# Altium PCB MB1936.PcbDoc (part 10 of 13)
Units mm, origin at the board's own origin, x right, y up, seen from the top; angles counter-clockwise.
Board outline 172 x 137 mm, 6 copper layers (Top Layer, Signal Layer 1, Signal Layer 2, Signal Layer 3, Signal Layer 4, Bottom Layer), stack 1.549 mm thick; 859 components, 672 nets, 3477 pads, 2222 vias.
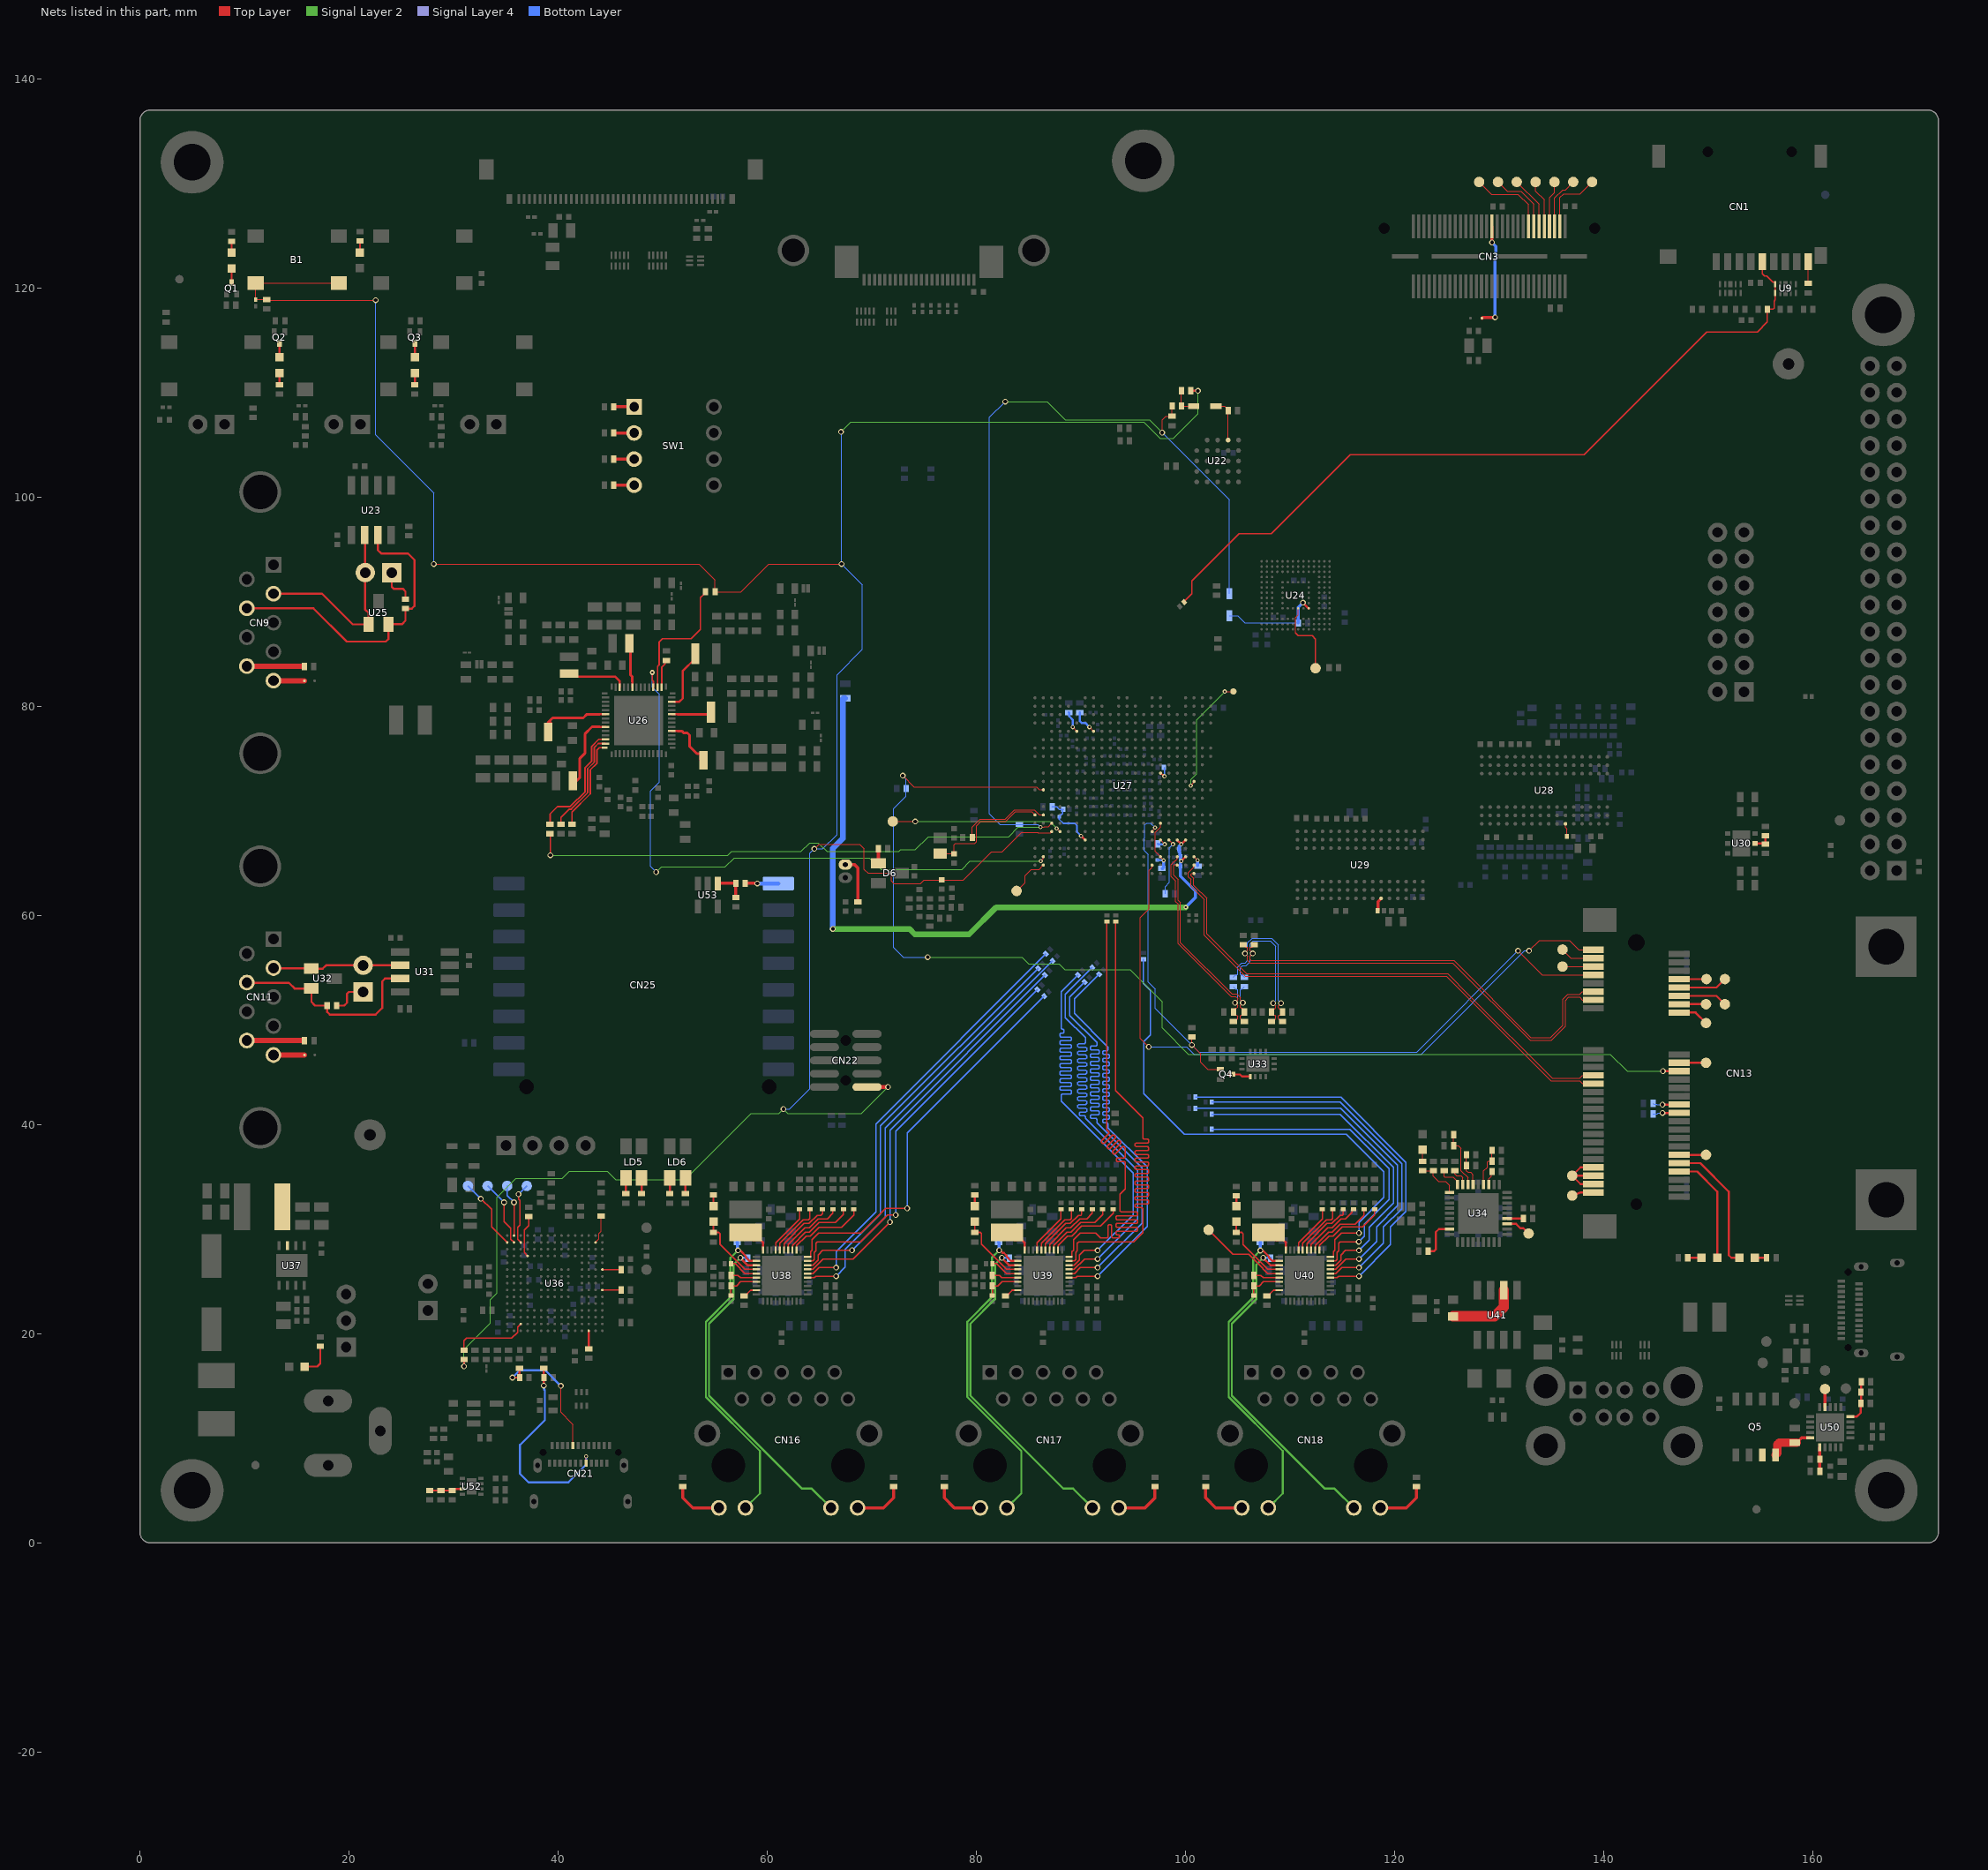
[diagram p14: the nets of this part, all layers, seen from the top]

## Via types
v1: diameter 0.55, hole 0.35, Top Layer to Bottom Layer, 1661 vias
v2: diameter 0.4, hole 0.2, Top Layer to Bottom Layer, tented both sides, 253 vias
v3: diameter 0.5, hole 0.2, Top Layer to Bottom Layer, 157 vias
v4: diameter 0.5, hole 0.25, Top Layer to Bottom Layer, 145 vias
v5: diameter 0.4, hole 0.2, Top Layer to Bottom Layer, 6 vias

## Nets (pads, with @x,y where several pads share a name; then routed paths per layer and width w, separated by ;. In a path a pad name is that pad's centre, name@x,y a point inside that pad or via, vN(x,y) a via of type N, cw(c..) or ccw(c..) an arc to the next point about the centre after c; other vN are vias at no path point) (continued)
NetC235_2: C235.2 C244.2 R267.1 U27.V7 | length 5.8
  Top Layer w0.2: v2(90,67.6) U27.V7@90.4,67.2
  Bottom Layer w0.15: R267.1@87.25,70.375 87.675,70.375 87.925,70.125 C235.2@88.238,70.125 ; C235.2@88.3,70.125 88.238,70.063 88.238,69.738 C244.2@87.925,69.425 87.925,69.175 88.3,68.8 89.4,68.8 89.6,68.6 89.6,67.999 v2(90,67.6)
NetC249_2: C249.2 C252.2 C260.2 R249.2 U27.V18 U27.V19 U27.Y19 | length 66.6
  Top Layer w0.2: U27.V18@99.2,67.2 v2(99.6,66.8) ; v2(99.6,65.2) U27.Y19@100,65.6 ; v2(99.6,66.8) U27.V19@100,67.2
  Signal Layer 2 w0.55: v1(66.275,58.7) 73.591,58.7 74.116,58.175 79.3,58.175 81.9,60.775 v2(100.025,60.775)
  Bottom Layer w0.3: v2(99.6,66.8) 99.397,66.597 99.397,66.347 C249.2@99.375,66.325 99.4,66.3 99.4,66.05 99.475,65.975 99.475,65.7 C252.2@99.5,65.675 99.5,65.326 99.6,65.227 v2(99.6,65.2) 99.6,65.173 99.5,65.073 C260.2@99.5,64.675 99.5,63.761 100.95,62.311 100.95,61.7 v2(100.025,60.775)
  Bottom Layer w0.55: v1(66.275,58.7) 66.275,66.4 67.225,67.35 67.225,80.705 67.27,80.75 R249.2@67.45,80.75
NetC251_2: C251.2 R286.2 U27.T16 U27.Y16 | length 5.5
  Top Layer w0.1: U27.T16@97.6,68.8 97.6,68.425 97.1,67.925 97.1,66.1 U27.Y16@97.6,65.6 97.6,65.575 97.906,65.269 v2(97.906,65.243)
  Bottom Layer w0.2: C251.2@97.3,65.3 97.329,65.272 97.878,65.272 v2(97.906,65.243)
  Bottom Layer w0.3: R286.2@97.795,64.475 97.9,64.58 v2@97.9,65.238
NetCN1_5: CN1.5 R13.1 R247.2 U9.1 U9.10 | length 74.7
  Top Layer w0.11: R247.2@99.862,89.962 99.862,89.987 100.621,90.746 100.621,91.996 105.11,96.485 108.185,96.485 115.75,104.05 138.1,104.05 149.825,115.775 154.675,115.775 155.64,116.74 R13.1@155.64,117.95 156.174,117.95 156.275,118.05 156.275,118.735 156.375,118.835 U9.1@156.375,119.52 156.375,120.496 156.33,120.541 156.174,120.541 155.59,121.125 155.35,121.125 155.15,121.325 CN1.5@155.15,122.5
NetCN1_9: CN1.9 R6.2 | length 2.1
  Top Layer w0.1: R6.2@159.55,120.425 CN1.9@159.55,122.5
NetCN3_32: CN3.32 SB1.1 | length 10.2
  Top Layer w0.3: SB1.1@128.35,117.1 128.425,117.175 v1(129.6,117.175) ; v1(129.3,124.34) CN3.32@129.3,125.87
  Bottom Layer w0.3: v1@129.3,124.339 129.675,123.964 129.675,122.783 129.6,122.708 v1(129.6,117.175)
NetCN3_46: CN3.46 TP1.1 | length 7.7
  Top Layer w0.1: TP1.1@128.075,130.125 129.25,128.95 131.8,128.95 132.8,127.95 CN3.46@132.8,125.87
NetCN3_48: CN3.48 TP2.1 | length 6.4
  Top Layer w0.1: TP2.1@129.875,130.125 130.76,129.24 132.06,129.24 133.3,128 CN3.48@133.3,125.87
NetCN3_50: CN3.50 TP3.1 | length 5.1
  Top Layer w0.1: TP3.1@131.675,130.125 133.8,128 CN3.50@133.8,125.87
NetCN3_52: CN3.52 TP4.1 | length 4.6
  Top Layer w0.1: TP4.1@133.475,130.125 133.475,129.245 134.3,128.42 CN3.52@134.3,125.87
NetCN3_54: CN3.54 TP5.1 | length 4.5
  Top Layer w0.1: CN3.54@134.8,125.87 134.8,128.65 135.275,129.125 TP5.1@135.275,130.125
NetCN3_56: CN3.56 TP6.1 | length 5.1
  Top Layer w0.1: CN3.56@135.3,125.87 135.3,128.6 136.075,129.375 136.325,129.375 TP6.1@137.075,130.125
NetCN3_58: CN3.58 TP7.1 | length 6.5
  Top Layer w0.1: CN3.58@135.8,125.87 135.8,128.625 136.15,128.975 137.725,128.975 TP7.1@138.875,130.125
NetCN9_2: CN9.2 JP1.2 U23.6 U25.1 | length 19
  Top Layer w0.2: CN9.2@12.77,90.75 17.425,90.75 20.354,87.821 U25.1@21.859,87.821 ; U23.6@21.549,96.316 21.549,89.226 21.869,88.906 21.869,87.831 U25.1@21.859,87.821 ; U25.1@21.844,87.806 U25.1@21.859,87.821 ; U25.1@21.869,87.821 U25.1@21.859,87.821
NetCN9_5: CN9.5 SB2.2 | length 3
  Top Layer w0.5: CN9.5@12.787,82.425 SB2.2@15.747,82.425
NetCN9_7: CN9.7 R40.1 U23.7 U25.2 | length 30
  Top Layer w0.2: CN9.7@10.23,89.365 16.585,89.365 19.775,86.175 23.525,86.175 23.769,86.419 U25.2@23.769,87.821 ; U23.7@22.764,96.361 22.764,94.921 23.081,94.603 25.621,94.603 26.254,93.971 26.254,89.581 26.004,89.331 25.399,89.331 25.399,88.181 25.049,87.831 U25.2@23.769,87.831
NetCN9_9: CN9.9 R50.2 | length 5.5
  Top Layer w0.2: R50.2@15.737,83.81 R50.2@15.747,83.8
  Top Layer w0.5: CN9.9@10.247,83.81 R50.2@15.737,83.81
NetCN11_2: CN11.2 JP2.2 U31.6 U32.1 | length 12.3
  Top Layer w0.2: CN11.2@12.77,54.925 16.38,54.925 U32.1@16.405,54.9 17.48,54.9 17.8,55.22 JP2.2@21.355,55.22 U31.6@24.89,55.22
NetCN11_5: CN11.5 SB3.2 | length 3
  Top Layer w0.5: CN11.5@12.79,46.65 SB3.2@15.75,46.65
NetCN11_7: CN11.7 R80.1 U31.7 U32.2 | length 19.9
  Top Layer w0.2: CN11.7@10.23,53.54 14.26,53.54 14.8,53 U32.2@16.405,53 16.405,51.72 16.755,51.37 R80.1@17.905,51.37 17.905,50.765 18.155,50.515 22.545,50.515 23.178,51.148 23.178,53.688 23.44,53.95 U31.7@24.89,53.95
NetCN11_9: CN11.9 R86.2 | length 5.5
  Top Layer w0.2: R86.2@15.74,48.035 R86.2@15.75,48.025
  Top Layer w0.5: CN11.9@10.25,48.035 R86.2@15.74,48.035
NetCN12_1: CN12.1 R66.1 | length 4.6
  Top Layer w0.3: CN12.1@67.475,64.85 68.35,64.85 68.675,64.525 R66.1@68.675,61.295
NetCN13_3: CN13.3 TP14.1 | length 3.3
  Top Layer w0.1: TP14.1@136.05,56.725 136.05,56.7 136.85,55.9 CN13.3@139,55.9
NetCN13_5: CN13.5 TP15.1 | length 2.4
  Top Layer w0.1: 136.55,55.1 CN13.5@139,55.1
NetCN13_8: CN13.8 TP16.1 | length 2.6
  Top Layer w0.2: CN13.8@147.243,53.9 TP16.1@149.818,53.9
NetCN13_10: CN13.10 TP17.1 | length 4.7
  Top Layer w0.2: CN13.10@147.2,53.1 150.775,53.1 TP17.1@151.575,53.9
NetCN13_12: CN13.12 TP19.1 | length 4.7
  Top Layer w0.2: CN13.12@147.2,52.3 150.775,52.3 TP19.1@151.575,51.5
NetCN13_14: CN13.14 TP18.1 | length 2.6
  Top Layer w0.2: CN13.14@147.2,51.5 TP18.1@149.775,51.5
NetCN13_16: CN13.16 TP20.1 | length 3
  Top Layer w0.2: CN13.16@147.2,50.7 148.775,50.7 TP20.1@149.775,49.7
NetCN13_20: CN13.20 TP21.1 | length 2.6
  Top Layer w0.2: CN13.20@147.2,45.9 TP21.1@149.775,45.9
NetCN13_30: CN13.30 R290.1 | length 2.6
  Top Layer w0.2: v1(145.614,41.9) CN13.30@147.2,41.9
  Bottom Layer w0.1: R290.1@144.7,42.025 144.791,41.934 145.046,41.934 145.08,41.9 v1(145.614,41.9)
NetCN13_32: CN13.32 R291.1 | length 2.5
  Top Layer w0.2: v1(145.614,41.1) CN13.32@147.2,41.1
  Bottom Layer w0.1: R291.1@144.7,41 145.107,41 145.207,41.1 v1(145.614,41.1)
NetCN13_42: CN13.42 TP23.1 | length 2.6
  Top Layer w0.2: CN13.42@147.2,37.1 TP23.1@149.775,37.1
NetCN13_44: CN13.44 LD10.2 | length 13
  Top Layer w0.2: CN13.44@147.2,36.3 149.225,36.3 151.937,33.587 151.937,27.513 152.2,27.25 LD10.2@152.875,27.25
NetCN13_45: CN13.45 CN13.47 CN13.49 TP24.1 | length 6.7
  Top Layer w0.2: CN13.49@139,34.3 137.775,34.3 TP24.1@136.975,35.1 ; CN13.47@139,35.1 TP24.1@136.975,35.1 ; CN13.45@139,35.9 137.775,35.9 TP24.1@136.975,35.1
NetCN13_46: CN13.46 LED2.2 | length 10.8
  Top Layer w0.2: CN13.46@147.2,35.5 148.921,35.5 150.85,33.571 LED2.2@150.85,27.25
NetCN13_51: CN13.51 TP25.1 | length 2.1
  Top Layer w0.2: TP25.1@136.975,33.2 137.775,33.5 CN13.51@139,33.5
NetCN16_11: CN16.11 R233.1 | length 4.9
  Top Layer w0.3: R233.1@51.925,5.375 51.925,4.3 52.885,3.34 CN16.11@55.37,3.34
NetCN16_12: CN16.12 R319.2 U38.32 | length 31.6
  Top Layer w0.2: v1(57.196,27.965) 57.263,27.898 57.449,27.898 57.961,27.386 57.961,27.289 58.3,26.95 U38.32@58.95,26.95
  Signal Layer 2 w0.2: v1(57.196,27.965) 56.475,27.244 56.475,23.475 54.125,21.125 54.125,13.951 59.3,8.776 59.3,4.73 CN16.12@57.91,3.34
  Bottom Layer w0.3: R319.2@57.125,28.725 57.161,28.689 57.161,28 v1(57.196,27.965)
NetCN16_13: CN16.13 R322.2 U38.33 | length 33.1
  Top Layer w0.2: v1(57.425,27.25) 57.425,27.233 58.108,26.55 U38.33@58.95,26.55
  Signal Layer 2 w0.2: v1(57.425,27.25) 56.775,26.6 56.775,23.297 54.425,20.947 54.425,14.075 63.325,5.175 64.255,5.175 CN16.13@66.09,3.34
  Bottom Layer w0.2: v1(57.425,27.25) 58.1,27.25 R322.2@58.15,27.2
NetCN16_14: CN16.14 R234.2 | length 4.9
  Top Layer w0.3: CN16.14@68.63,3.34 71.115,3.34 72.075,4.3 R234.2@72.075,5.375
NetCN17_11: CN17.11 R235.1 | length 4.9
  Top Layer w0.3: R235.1@76.925,5.375 76.925,4.3 77.885,3.34 CN17.11@80.37,3.34
NetCN17_12: CN17.12 R317.2 U39.32 | length 31.6
  Top Layer w0.2: v1(82.177,27.969) 82.272,27.969 82.516,27.725 82.622,27.725 82.9,27.447 82.9,27.35 83.3,26.95 U39.32@83.95,26.95
  Signal Layer 2 w0.2: v1(82.177,27.969) 81.475,27.267 81.475,23.475 79.125,21.125 79.125,13.951 84.3,8.776 84.3,4.73 CN17.12@82.91,3.34
  Bottom Layer w0.3: R317.2@82.125,28.725 82.151,28.699 82.151,27.995 v1(82.177,27.969)
NetCN17_13: CN17.13 R321.2 U39.33 | length 33.1
  Top Layer w0.2: v1(82.425,27.25) 82.425,27.233 83.108,26.55 U39.33@83.95,26.55
  Signal Layer 2 w0.2: v1(82.425,27.25) 81.775,26.6 81.775,23.297 79.425,20.947 79.425,14.075 88.325,5.175 89.255,5.175 CN17.13@91.09,3.34
  Bottom Layer w0.2: v1(82.425,27.25) 83.1,27.25 R321.2@83.15,27.2
NetCN17_14: CN17.14 R236.2 | length 4.9
  Top Layer w0.3: CN17.14@93.63,3.34 96.115,3.34 97.075,4.3 R236.2@97.075,5.375
NetCN18_11: CN18.11 R237.1 | length 4.9
  Top Layer w0.3: R237.1@101.925,5.375 101.925,4.3 102.885,3.34 CN18.11@105.37,3.34
NetCN18_12: CN18.12 R315.2 U40.32 | length 31.6
  Top Layer w0.2: v1(107.148,27.951) 107.215,27.884 107.463,27.884 107.961,27.386 107.961,27.289 108.3,26.95 U40.32@108.95,26.95
  Signal Layer 2 w0.2: v1(107.148,27.951) 106.475,27.277 106.475,23.475 104.125,21.125 104.125,13.951 109.3,8.776 109.3,4.73 CN18.12@107.91,3.34
  Bottom Layer w0.3: R315.2@107.125,28.725 107.137,28.713 107.137,27.963 v1(107.148,27.951)
NetCN18_13: CN18.13 R320.2 U40.33 | length 33.1
  Top Layer w0.2: v1(107.425,27.25) 107.425,27.233 108.108,26.55 U40.33@108.95,26.55
  Signal Layer 2 w0.2: v1(107.425,27.25) 106.775,26.6 106.775,23.297 104.425,20.947 104.425,14.075 113.325,5.175 114.255,5.175 CN18.13@116.09,3.34
  Bottom Layer w0.2: v1(107.425,27.25) 108.1,27.25 R320.2@108.15,27.2
NetCN18_14: CN18.14 R238.2 | length 4.9
  Top Layer w0.3: CN18.14@118.63,3.34 121.115,3.34 122.075,4.3 R238.2@122.075,5.375
NetCN21_A5: CN21.A5 R217.2 R221.1 | length 13.6
  Top Layer w0.1: v1(40.252,15.008) 40.25,15.006 40.25,12.475 41.25,11.475 ; 41,11.725 41.25,11.475 ; CN21.A5@41.415,9.31 41.415,11.31 41.25,11.475
  Top Layer w0.2: v1(35.63,15.8) R221.1@36.305,15.8 R217.2@36.305,16.7
  Bottom Layer w0.2: v1(35.63,15.8) 36.33,16.5 38.76,16.5 v1(40.252,15.008)
NetCN21_B5: CN21.B5 R218.2 R222.1 | length 19.9
  Top Layer w0.1: CN21.B5@42.665,7.61 v5(42.665,8.27)
  Top Layer w0.2: v1(38.625,15.03) R222.1@38.625,15.8 R218.2@38.625,16.7
  Bottom Layer w0.2: v1(38.625,15.03) 38.652,15.003 38.652,14.644 38.725,14.572 38.725,11.725 36.35,9.35 36.35,6.6 37.175,5.775 40.975,5.775 42.665,7.465 v5(42.665,8.27)
NetCN25_1: CN25.1 R243.1 | length 3.2
  Top Layer w0.3: R243.1@57.887,63.063 59.022,63.063 v1(59.04,63.045)
  Bottom Layer w0.4: v1@59.045,63.04 CN25.1@61.055,63.04
NetD1_1: D1.1 R23.1 U22.A4 | length 4.2
  Top Layer w0.1: D1.1@102.9,108.7 103.736,108.7 104.066,108.37 U22.A4@104.066,105.441
NetD1_2: D1.2 R21.2 R22.2 | length 2.6
  Top Layer w0.1: R21.2@99.609,110.15 R22.2@99.609,108.7 D1.2@100.76,108.7
NetD5_1: D5.1 R248.1 U24.K5 | length 9.8
  Top Layer w0.2: v1(111.225,89.9) U24.K5@111.775,89.35
  Bottom Layer w0.1: D5.1@104.175,88.63 104.995,88.63 105.675,87.95 R248.1@110.775,87.95
  Bottom Layer w0.3: R248.1@110.775,87.95 110.775,89.45 v1(111.225,89.9)
NetD6_1: D6.1 R67.1 | length 1.4
  Top Layer w0.3: D6.1@70.625,64.975 R67.1@70.625,66.375
NetJP1_1: JP1.1 R40.2 | length 3.6
  Top Layer w0.2: JP1.1@24.089,92.781 24.089,91.411 24.269,91.231 25.133,91.231 25.399,90.965 R40.2@25.399,90.231
NetJP2_1: JP2.1 R80.2 | length 3.6
  Top Layer w0.2: R80.2@18.805,51.37 19.539,51.37 19.805,51.636 19.805,52.5 19.985,52.68 JP2.1@21.355,52.68
NetL1_1: L1.1 U26.37 | length 4.2
  Top Layer w0.21: U26.37@47.1,81.797 47.1,82.352
  Top Layer w0.25: L1.1@46.9,85.962 46.9,83 47.1,82.8 47.1,82.352
NetL2_1: L2.1 U26.26 | length 5.7
  Top Layer w0.2: U26.26@51.117,80.427 51.6,80.427 51.925,80.752 51.925,83.387 53.05,84.512 L2.1@53.05,85.027
NetL3_1: L3.1 U26.40 | length 5.9
  Top Layer w0.15: L3.1@40.898,82.989 L3.1@41.05,82.837
  Top Layer w0.21: L3.1@41.05,83.102 41.335,82.817 43.11,82.817 45.465,82.817 45.9,82.382 U26.40@45.9,81.797
NetL4_1: L4.1 U26.23 | length 3.8
  Top Layer w0.15: L4.1@54.56,78.712 L4.1@54.56,79.227
  Top Layer w0.21: U26.23@50.87,79.227 51.425,79.227
  Top Layer w0.25: 51.425,79.227 54.2,79.227
NetL5_1: L5.1 U26.48 | length 7.2
  Top Layer w0.15: L5.1@38.818,77.275 L5.1@39.07,77.527 ; L5.1@39.29,77.412 L5.1@39.29,77.927
  Top Layer w0.21: 43.975,79.227 U26.48@44.53,79.227
  Top Layer w0.25: 39.025,78.427 39.475,78.877 42.4,78.877 42.75,79.227 43.975,79.227 ; L5.1@39.29,77.927 39.29,78.442
NetL6_1: L6.1 U26.19 | length 5.7
  Top Layer w0.15: L6.1@53.63,74.37 L6.1@53.63,74.852 ; L6.1@53.85,74.852 L6.1@54.102,74.599
  Top Layer w0.21: U26.19@50.87,77.627 51.425,77.627
  Top Layer w0.25: 51.425,77.627 51.823,77.627 51.998,77.452 52.35,77.452 52.575,77.227 52.575,76.152 53.271,75.456 53.625,75.456 53.63,75.451 L6.1@53.63,74.852
NetL7_1: L7.1 U26.51 | length 7.4
  Top Layer w0.21: 43.975,78.027 U26.51@44.53,78.027
  Top Layer w0.25: L7.1@41.625,73.252 L7.1@41.625,73.496 ; L7.1@41.675,72.777 42.075,73.177 42.075,75.011 42.55,75.486 42.55,77.33 43.247,78.027 43.975,78.027
NetL8_1: L8.1 U37.7
NetL12_2: L12.2 U41.2 | length 6.8
  Top Layer w1: L12.2@125.575,21.65 129.55,21.65 130.43,22.53 U41.2@130.43,24.15
NetLD1_1: LD1.1 R3.2 | length 0.9
  Top Layer w0.2: LD1.1@21.047,123.55 R3.2@21.047,124.475
NetLD2_1: LD2.1 R20.1 | length 1
  Top Layer w0.2: R20.1@26.287,110.75 LD2.1@26.287,111.7
NetLD2_2: LD2.2 Q3.3 | length 1.2
  Top Layer w0.2: LD2.2@26.287,113.5 Q3.3@26.287,114.7
NetLD3_1: LD3.1 R19.1 | length 1
  Top Layer w0.2: R19.1@13.363,110.75 LD3.1@13.363,111.7
NetLD3_2: LD3.2 Q2.3 | length 1.3
  Top Layer w0.2: LD3.2@13.363,113.35 Q2.3@13.363,114.7
NetLD4_1: LD4.1 R4.2 | length 1.1
  Top Layer w0.2: LD4.1@8.773,123.35 R4.2@8.773,124.45
NetLD4_2: LD4.2 Q1.3 | length 1.2
  Top Layer w0.2: Q1.3@8.773,120.5 LD4.2@8.773,121.7
NetLD5_1: LD5.1 R131.1 | length 1.5
  Top Layer w0.2: R131.1@47.975,33.375 LD5.1@47.975,34.9
NetLD5_2: LD5.2 R130.2 | length 1.5
  Top Layer w0.2: R130.2@46.475,33.375 LD5.2@46.475,34.9
NetLD6_1: LD6.1 R133.1 | length 1.5
  Top Layer w0.2: R133.1@52.175,33.375 LD6.1@52.175,34.9
NetLD6_2: LD6.2 R132.1 | length 1.5
  Top Layer w0.2: R132.1@50.675,33.375 LD6.2@50.675,34.9
NetLD7_1: LD7.1 R158.2 U38.34 | length 7.2
  Top Layer w0.15: LD7.1@54.85,30.695 R158.2@54.85,29.67 55.382,29.67 55.47,29.582 55.47,28.555 57.875,26.15 U38.34@58.95,26.15
NetLD7_2: LD7.2 R126.1 | length 1.1
  Top Layer w0.2: LD7.2@54.85,32.195 R126.1@54.85,33.27
NetLD8_1: LD8.1 R159.2 U39.34 | length 7.2
  Top Layer w0.15: LD8.1@79.85,30.695 R159.2@79.85,29.67 80.382,29.67 80.47,29.582 80.47,28.555 82.875,26.15 U39.34@83.95,26.15
NetLD8_2: LD8.2 R127.1 | length 0.9
  Top Layer w0.2: LD8.2@79.85,32.325 R127.1@79.85,33.27
NetLD9_1: LD9.1 R160.2 U40.34 | length 7.2
  Top Layer w0.15: LD9.1@104.85,30.695 R160.2@104.85,29.67 105.38,29.67 105.5,29.55 105.5,28.525 107.875,26.15 U40.34@108.95,26.15
NetLD9_2: LD9.2 R128.1 | length 0.8
  Top Layer w0.2: LD9.2@104.85,32.375 R128.1@104.85,33.17
NetLD10_1: LD10.1 R172.2 | length 1.1
  Top Layer w0.2: LD10.1@154.525,27.25 R172.2@155.575,27.25
NetLD11_1: LD11.1 R210.1 | length 3.2
  Top Layer w0.2: LD11.1@15.775,16.85 16.95,16.85 17.25,17.15 R210.1@17.25,18.8
NetLD12_1: LD12.1 R101.1 | length 1.1
  Top Layer w0.1: R101.1@122.675,36.475 LD12.1@122.675,37.575
NetLE1_1: LE1.1 U38.30 | length 2.8
  Top Layer w0.2: LE1.1@57.925,29.675 58.675,28.925 59.375,28.925 59.6,28.7 U38.30@59.6,28
NetLE2_1: LE2.1 U39.30 | length 2.8
  Top Layer w0.2: LE2.1@82.925,29.675 83.675,28.925 84.375,28.925 84.6,28.7 U39.30@84.6,28
NetLE3_1: LE3.1 U40.30 | length 2.8
  Top Layer w0.2: LE3.1@107.925,29.675 108.675,28.925 109.375,28.925 109.6,28.7 U40.30@109.6,28
NetLED2_1: LED2.1 R171.1 | length 1.3
  Top Layer w0.2: R171.1@148.025,27.25 LED2.1@149.3,27.25
NetQ4_3: Q4.3 U33.1 | length 1.8
  Top Layer w0.2: Q4.3@104.425,44.79 105.2,44.79 105.4,44.59 U33.1@106.175,44.59
NetQ5_7: Q5.7 Q5.8 R225.2 U50.10 | length 4.5
  Top Layer w0.3: R225.2@158.43,9.575 158.905,10.05 U50.10@159.725,10.05
  Top Layer w0.8: Q5.8@156.425,8.4 156.6,8.575 156.6,9.399 156.776,9.575 R225.2@158.43,9.575
NetR38_2: R38.2 U26.31 | length 12.7
  Top Layer w0.15: U26.31@49.5,81.797 49.5,83.8 49.65,83.95 49.65,86.125 49.975,86.45 52.725,86.45 53.6,87.325 53.6,90.357 53.918,90.675 53.92,90.675 54.1,90.855 R38.2@54.1,90.95
NetR46_2: R46.2 U26.30 | length 2.8
  Top Layer w0.15: U26.30@49.9,81.797 49.9,83.697 50.232,84.029 50.232,84.257 R46.2@50.35,84.375
NetR59_2: R59.2 U26.54 | length 11.4
  Top Layer w0.15: R59.2@39.225,68.7 39.225,69.675 39.95,70.4 41.15,70.4 42.575,71.825 42.575,74.125 43.212,74.762 43.212,76.162 43.877,76.827 U26.54@44.53,76.827
NetR60_2: R60.2 U26.55 | length 10
  Top Layer w0.15: R60.2@40.275,68.7 40.275,69.353 41.072,70.15 41.254,70.15 42.825,71.721 42.825,74.021 43.462,74.659 43.462,76.059 43.831,76.427 U26.55@44.53,76.427
NetR61_2: R61.2 U26.56 | length 8.9
  Top Layer w0.15: R61.2@41.325,68.7 41.325,69.868 43.075,71.618 43.075,73.918 43.712,74.555 43.712,75.812 43.927,76.027 U26.56@44.455,76.027
NetR62_2: R62.2 R65.1 U30.5 | length 1.7
  Top Layer w0.2: U30.5@154.455,66.875 155.405,66.875 155.455,66.925 R62.2@155.455,67.6
NetR63_2: R63.2 U28.F9 | length 1.3
  Top Layer w0.09: U28.F9@136.325,68.75 136.325,68.4 136.475,68.25 R63.2@136.475,67.55
NetR68_1: R68.1 SW1.1 | length 1.9
  Top Layer w0.3: R68.1@45.325,108.625 SW1.1@47.265,108.625
NetR71_1: R71.1 SW1.2 | length 1.9
  Top Layer w0.3: R71.1@45.325,106.125 SW1.2@47.265,106.125
NetR73_2: R73.2 U29.F9 | length 1.3
  Top Layer w0.3: R73.2@118.375,60.425 118.375,60.475 118.418,60.517 118.418,61.317 118.7,61.599 U29.F9@118.7,61.625
NetR76_1: R76.1 SW1.3 | length 1.9
  Top Layer w0.3: R76.1@45.325,103.625 SW1.3@47.265,103.625
NetR79_1: R79.1 SW1.4 | length 1.9
  Top Layer w0.3: R79.1@45.325,101.125 SW1.4@47.265,101.125
NetR95_2: R95.2 R97.1 U34.25 | length 5.6
  Top Layer w0.1: R95.2@125.625,39.025 R97.1@125.625,37.975 126.1,37.975 126.35,37.725 126.35,35.575 127,34.925 U34.25@127,34.25
NetR98_2: R98.2 R100.1 U34.22 | length 3.8
  Top Layer w0.1: U34.22@128.5,34.25 128.5,35.554 128.85,35.904 128.85,36.4 128.95,36.5 R100.1@129.3,36.5 R98.2@129.3,37.525
NetR99_1: R99.1 R105.2 U34.24 | length 3.3
  Top Layer w0.1: R99.1@126.85,37.105 R105.2@126.85,36.08 126.85,35.584 127,35.434 127.256,35.434 127.495,35.195 127.495,34.255 U34.24@127.5,34.25
NetR101_2: R101.2 R102.2 U34.28 | length 4.1
  Top Layer w0.1: R101.2@122.675,35.575 R102.2@123.7,35.575 123.7,35.05 124.2,34.55 124.884,34.55 125.25,34.184 U34.28@125.25,33.5
NetR103_1: R103.1 U34.27 | length 2.3
  Top Layer w0.1: R103.1@124.725,35.575 124.725,35.034 124.784,34.975 125.575,34.975 126,34.55 U34.27@126,34.25
NetR104_2: R104.2 U34.26 | length 1.9
  Top Layer w0.1: R104.2@125.75,35.575 125.75,35.25 125.9,35.1 126.341,35.1 126.5,34.941 U34.26@126.5,34.25
NetR106_1: R106.1 U34.21 | length 1.4
  Top Layer w0.1: U34.21@129,34.25 129,34.825 129.234,35.059 129.234,35.434 R106.1@129.3,35.5
NetR135_2: R135.2 U38.27 | length 4.8
  Top Layer w0.11: U38.27@60.8,28 60.8,28.675 63.075,30.95 R135.2@63.075,31.9
NetR136_2: R136.2 U38.26 | length 5.4
  Top Layer w0.11: U38.26@61.2,28 61.2,28.65 63.45,30.9 63.95,30.9 64.075,31.025 R136.2@64.075,31.9
NetR137_2: R137.2 U38.25 | length 5.9
  Top Layer w0.11: U38.25@61.6,28 61.6,28.6 63.525,30.525 63.975,30.525 64.775,31.325 65.125,31.325 65.275,31.475 ; 65.275,31.5 65.275,31.475 ; R137.2@65.275,31.9 65.275,31.475
NetR138_2: R138.2 U38.24 | length 6.4
  Top Layer w0.11: U38.24@62,28 62,28.525 63.587,30.113 64.012,30.113 64.875,30.975 65.75,30.975 66.275,31.5 R138.2@66.275,31.9
NetR139_2: R139.2 U38.23 | length 7
  Top Layer w0.11: U38.23@62.4,28 62.4,28.45 63.662,29.713 64.037,29.713 64.95,30.625 66.5,30.625 67.275,31.4 R139.2@67.275,31.9
NetR140_2: R140.2 U38.22 | length 7.7
  Top Layer w0.11: U38.22@62.8,28 62.8,28.425 63.712,29.338 64.112,29.338 64.95,30.175 67.1,30.175 68.275,31.35 R140.2@68.275,31.9
NetR141_2: R141.2 U39.27 | length 4.8
  Top Layer w0.11: U39.27@85.8,28 85.8,28.675 88.075,30.95 R141.2@88.075,31.9
NetR142_2: R142.2 U39.26 | length 5.4
  Top Layer w0.11: U39.26@86.2,28 86.2,28.65 88.45,30.9 88.95,30.9 89.075,31.025 R142.2@89.075,31.9
NetR143_2: R143.2 U39.25 | length 5.7
  Top Layer w0.11: U39.25@86.6,28 86.6,28.6 88.525,30.525 88.975,30.525 89.775,31.325 90.011,31.325 90.075,31.389 R143.2@90.075,31.9
NetR144_2: R144.2 U39.24 | length 6.2
  Top Layer w0.11: U39.24@87,28 87,28.525 88.587,30.113 89.012,30.113 89.875,30.975 90.55,30.975 91.075,31.5 R144.2@91.075,31.9
NetR145_2: R145.2 U39.23 | length 6.8
  Top Layer w0.11: U39.23@87.4,28 87.4,28.45 88.662,29.713 89.037,29.713 89.95,30.625 91.3,30.625 92.075,31.4 R145.2@92.075,31.9
NetR146_2: R146.2 U39.22 | length 7.4
  Top Layer w0.11: U39.22@87.8,28 87.8,28.425 88.712,29.338 89.112,29.338 90.075,30.3 91.875,30.3 93.075,31.5 R146.2@93.075,31.9
NetR147_2: R147.2 U40.27 | length 4.8
  Top Layer w0.11: U40.27@110.8,28 110.8,28.675 113.075,30.95 R147.2@113.075,31.9
NetR148_2: R148.2 U40.26 | length 5.4
  Top Layer w0.11: U40.26@111.2,28 111.2,28.65 113.45,30.9 113.95,30.9 114.075,31.025 R148.2@114.075,31.9
NetR149_2: R149.2 U40.25 | length 5.7
  Top Layer w0.11: U40.25@111.6,28 111.6,28.6 113.525,30.525 113.975,30.525 114.775,31.325 115.011,31.325 115.075,31.389 R149.2@115.075,31.9
NetR150_2: R150.2 U40.24 | length 6.1
  Top Layer w0.11: U40.24@112,28 112,28.525 113.587,30.113 114.012,30.113 114.875,30.975 115.3,30.975 115.924,31.599 115.924,31.755 116.069,31.9 R150.2@116.075,31.9
NetR151_2: R151.2 U40.23 | length 6.9
  Top Layer w0.11: U40.23@112.4,28 112.4,28.45 113.662,29.713 114.037,29.713 114.8,30.475 116.233,30.475 117.075,31.317 R151.2@117.075,31.9
NetR152_2: R152.2 U40.22 | length 7.5
  Top Layer w0.11: U40.22@112.8,28 112.8,28.425 113.712,29.338 114.112,29.338 114.975,30.2 116.925,30.2 118.075,31.35 R152.2@118.075,31.9
NetR155_2: R155.2 U36.B14 | length 2.7
  Top Layer w0.1: U36.B14@43.575,28.725 43.9,29.05 43.9,29.575 44.1,29.775 R155.2@44.1,31.25
NetR156_1: R156.1 U36.D4 | length 4.1
  Top Layer w0.12: U36.D4@37.075,27.425 36.75,27.75 36.75,29.9 37.2,30.35 R156.1@37.2,31.2
NetR157_1: R157.1 U34.13 | length 1.6
  Top Layer w0.2: U34.13@130.75,31 R157.1@132.311,31
NetR161_2: R161.2 U38.20 | length 38
  Top Layer w0.11: U38.20@63.85,27.35 64.1,27.35 64.145,27.395 64.145,27.837 64.28,27.972 64.28,28.98 64.915,29.615 68.965,29.615 71.325,31.975 v1(73.375,31.975)
  Bottom Layer w0.11: v1(73.375,31.975) 73.375,39.175 R161.2@86.475,52.275
NetR162_2: R162.2 U39.20 | length 60.5
  Top Layer w0.11: U39.20@88.85,27.35 89.1,27.35 89.145,27.395 89.145,27.837 89.28,27.972 89.28,28.98 89.915,29.615 91.385,29.615 91.85,29.15 92.431,29.15 92.486,29.15 92.577,29.241 92.577,30.329 92.668,30.42 92.85,30.42 92.941,30.329 92.941,29.241 93.032,29.15 93.277,29.15 93.6,29.15 93.673,29.223 93.673,29.352 93.582,29.443 93.44,29.443 93.349,29.534 93.349,29.716 93.44,29.807 95.34,29.807 95.431,29.898 95.431,30.08 95.34,30.171 93.44,30.171 93.349,30.262 93.349,30.444 93.44,30.535 95.34,30.535 95.431,30.626 95.431,30.808 95.34,30.899 93.44,30.899 93.349,30.99 93.349,31.172 93.44,31.263 95.34,31.263 95.431,31.354 95.431,31.536 95.34,31.627 93.836,31.627 93.745,31.718 93.745,32.005 93.745,33.32 94.25,33.825 94.25,36.356 94.159,36.447 93.483,36.447 93.392,36.538 93.392,36.72 93.483,36.811 94.159,36.811 94.25,36.902 94.25,37.425 94.25,37.725 94.103,37.872 93.975,37.872 93.256,37.153 93.128,37.153 92.999,37.282 92.999,37.411 93.8,38.211 93.8,38.34 93.671,38.469 93.542,38.469 92.741,37.668 92.613,37.668 92.484,37.797 92.484,37.925 93.285,38.726 93.285,38.855 93.156,38.983 93.027,38.983 92.227,38.183 92.098,38.183 91.969,38.311 91.969,38.44 92.688,39.159 92.688,39.287 92.596,39.379 92.557,39.418 92.475,39.5 R162.2@92.475,59.4
NetR163_2: R163.2 U40.20 | length 50.8
  Top Layer w0.11: U40.20@113.85,27.35 114.1,27.35 114.145,27.395 114.145,27.837 114.28,27.972 114.28,28.98 114.915,29.615 v1(116.58,29.615)
  Bottom Layer w0.11: R163.2@95.975,55.8 95.975,53.514 96.65,52.839 96.65,48.575 96.013,47.938 96.013,42.93 99.868,39.075 115.375,39.075 118.968,35.482 118.968,33.018 116.58,30.63 v1(116.58,29.615)
NetR164_2: R164.2 U38.19 | length 38.3
  Top Layer w0.11: U38.19@63.85,26.95 64.37,26.95 64.49,27.07 64.49,27.78 64.64,27.93 64.64,28.64 64.79,28.79 68.915,28.79 71.475,31.35 v1(72.275,31.35)
  Bottom Layer w0.11: v1(72.275,31.35) 72.275,39.35 R164.2@85.838,52.913
NetR165_2: R165.2 U39.19 | length 60.9
  Top Layer w0.11: U39.19@88.85,26.95 89.37,26.95 89.49,27.07 89.49,27.78 89.64,27.93 89.64,28.64 89.79,28.79 95.015,28.79 95.9,29.675 95.9,31.9 95.9,31.955 95.809,32.046 95.27,32.046 95.179,32.137 95.179,32.319 95.27,32.41 96.37,32.41 96.461,32.501 96.461,32.683 96.37,32.774 95.27,32.774 95.179,32.865 95.179,33.047 95.27,33.138 96.37,33.138 96.461,33.229 96.461,33.411 96.37,33.502 95.27,33.502 95.179,33.593 95.179,33.775 95.27,33.866 96.37,33.866 96.461,33.957 96.461,34.139 96.37,34.23 95.27,34.23 95.179,34.321 95.179,34.503 95.27,34.594 96.37,34.594 96.461,34.685 96.461,34.867 96.37,34.958 95.27,34.958 95.179,35.049 95.179,35.231 95.27,35.322 96.37,35.322 96.461,35.413 96.461,35.595 96.37,35.686 95.27,35.686 95.179,35.777 95.179,35.959 95.27,36.05 96.37,36.05 96.461,36.141 96.461,36.323 96.37,36.414 95.27,36.414 95.179,36.505 95.179,36.687 95.27,36.778 96.37,36.778 96.461,36.869 96.461,37.051 96.37,37.142 95.27,37.142 95.179,37.233 95.179,37.415 95.27,37.506 96.37,37.506 96.461,37.597 96.461,37.779 96.37,37.87 95.27,37.87 95.179,37.961 95.179,38.143 95.27,38.234 96.37,38.234 96.461,38.325 96.461,38.507 96.37,38.598 95.991,38.598 95.9,38.689 95.9,38.762 95.9,40.65 93.319,43.231 93.319,59.394 R165.2@93.325,59.4
NetR166_2: R166.2 U40.19 | length 31
  Top Layer w0.11: U40.19@113.85,26.95 114.37,26.95 114.49,27.07 114.49,27.78 114.64,27.93 114.64,28.64 114.79,28.79 115.89,28.79 v1(116.565,28.79)
  Bottom Layer w0.11: R166.2@102.5,39.55 115.7,39.55 119.464,35.786 119.464,32.825 117.1,30.461 117.1,29.325 v1(116.565,28.79)
NetR167_2: R167.2 U38.18 | length 40.8
  Top Layer w0.11: U38.18@63.85,26.55 64.35,26.55 64.85,27.05 64.85,27.525 65.3,27.975 v1(68.1,27.975)
  Bottom Layer w0.11: v1(68.1,27.975) 71.275,31.15 71.275,39.65 R167.2@87.288,55.663
NetR168_2: R168.2 U39.18 | length 51.3
  Top Layer w0.11: U39.18@88.85,26.55 89.35,26.55 89.85,27.05 89.85,27.525 90.29,27.965 v1(91.58,27.965)
  Bottom Layer w0.11: R168.2@89.713,54.288 88.1,52.675 88.1,49.55 88.1,49.189 88.191,49.098 88.273,49.098 88.364,49.007 88.364,48.825 88.273,48.734 88.08,48.734 87.989,48.643 87.989,48.461 88.08,48.37 89.012,48.37 89.103,48.279 89.103,48.097 89.012,48.006 88.08,48.006 87.989,47.915 87.989,47.733 88.08,47.642 89.012,47.642 89.103,47.551 89.103,47.369 89.012,47.278 88.08,47.278 87.989,47.187 87.989,47.005 88.08,46.914 89.012,46.914 89.103,46.823 89.103,46.641 89.012,46.55 88.08,46.55 87.989,46.459 87.989,46.277 88.08,46.186 89.012,46.186 89.103,46.095 89.103,45.913 89.012,45.822 88.08,45.822 87.989,45.731 87.989,45.549 88.08,45.458 89.012,45.458 89.103,45.367 89.103,45.185 89.012,45.094 88.08,45.094 87.989,45.003 87.989,44.821 88.08,44.73 89.012,44.73 89.103,44.639 89.103,44.457 89.012,44.366 88.08,44.366 87.989,44.275 87.989,44.093 88.08,44.002 89.012,44.002 89.103,43.911 89.103,43.729 89.012,43.638 88.08,43.638 87.989,43.547 87.989,43.365 88.08,43.274 89.012,43.274 89.103,43.183 89.103,43.001 89.012,42.91 88.191,42.91 88.1,42.819 88.1,42.4 88.1,42.25 94.975,35.375 94.975,31.36 v1(91.58,27.965)
NetR169_2: R169.2 U40.18 | length 32.4
  Top Layer w0.11: U40.18@113.85,26.55 114.35,26.55 114.85,27.05 114.85,27.525 115.29,27.965 v1(116.58,27.965)
  Bottom Layer w0.11: R169.2@102.5,40.986 114.789,40.986 119.875,35.9 119.875,32.5 117.557,30.182 117.557,28.943 v1(116.58,27.965)
NetR170_2: R170.2 U34.35 | length 3.9
  Top Layer w0.2: R170.2@123.2,27.875 123.75,27.875 123.925,28.05 123.925,29.697 124.228,30 U34.35@125.25,30
NetR173_2: R173.2 U38.17 | length 39.5
  Top Layer w0.11: U38.17@63.85,26.15 64.34,26.15 65.33,27.14 68.19,27.14 v1(71.725,30.675)
  Bottom Layer w0.11: v1(71.725,30.675) 71.725,39.45 R173.2@86.563,54.288
NetR174_2: R174.2 U39.17 | length 51
  Top Layer w0.11: U39.17@88.85,26.15 89.34,26.15 90.33,27.14 v1(91.58,27.14)
  Bottom Layer w0.11: R174.2@91.088,55.013 88.5,52.425 88.5,50.225 90.425,48.3 90.425,48.075 90.425,47.828 90.334,47.737 89.781,47.737 89.69,47.646 89.69,47.464 89.781,47.373 90.452,47.373 90.543,47.282 90.543,47.1 90.452,47.009 89.781,47.009 89.69,46.918 89.69,46.736 89.781,46.645 90.452,46.645 90.543,46.554 90.543,46.372 90.452,46.281 89.781,46.281 89.69,46.19 89.69,46.008 89.781,45.917 90.452,45.917 90.543,45.826 90.543,45.644 90.452,45.553 89.781,45.553 89.69,45.462 89.69,45.28 89.781,45.189 90.452,45.189 90.543,45.098 90.543,44.916 90.452,44.825 89.781,44.825 89.69,44.734 89.69,44.552 89.781,44.461 90.452,44.461 90.543,44.37 90.543,44.188 90.452,44.097 89.781,44.097 89.69,44.006 89.69,43.824 89.781,43.733 90.452,43.733 90.543,43.642 90.543,43.46 90.452,43.369 89.781,43.369 89.69,43.278 89.69,43.096 89.781,43.005 90.452,43.005 90.543,42.914 90.543,42.732 90.452,42.641 89.781,42.641 89.69,42.55 89.69,42.368 89.781,42.277 90.452,42.277 90.543,42.186 90.543,42.004 90.452,41.913 89.781,41.913 89.69,41.822 89.69,41.64 89.781,41.549 90.452,41.549 90.543,41.458 90.543,41.276 90.452,41.185 89.917,41.185 89.826,41.094 89.826,40.912 89.917,40.821 90.334,40.821 90.425,40.73 90.425,40.575 95.4,35.6 95.4,30.96 v1(91.58,27.14)
NetR175_2: R175.2 U40.17 | length 35.2
  Top Layer w0.11: U40.17@113.85,26.15 114.34,26.15 115.33,27.14 v1(116.58,27.14)
  Bottom Layer w0.11: R175.2@100.95,41.553 114.822,41.553 120.275,36.1 120.275,32.225 118.274,30.224 118.274,28.834 v1(116.58,27.14)
NetR176_2: R176.2 U38.35 | length 2.8
  Top Layer w0.11: R176.2@56.525,26.7 56.925,26.7 57.875,25.75 U38.35@58.95,25.75
NetR177_2: R177.2 U39.35 | length 2.8
  Top Layer w0.11: R177.2@81.525,26.7 81.925,26.7 82.875,25.75 U39.35@83.95,25.75
NetR178_2: R178.2 U38.16 | length 41.3
  Top Layer w0.11: U38.16@63.85,25.75 64.375,25.75 64.94,26.315 v1(66.58,26.315)
  Bottom Layer w0.11: v1(66.58,26.315) 66.58,27.855 70.375,31.65 70.375,40.05 R178.2@86.638,56.313
NetR179_2: R179.2 U39.16 | length 49.6
  Top Layer w0.11: U39.16@88.85,25.75 89.375,25.75 89.94,26.315 v1(91.58,26.315)
  Bottom Layer w0.11: R179.2@90.363,53.638 88.925,52.2 88.925,50.425 91.525,47.825 91.525,47.7 91.525,47.578 91.434,47.487 91.002,47.487 90.911,47.396 90.911,47.214 91.002,47.123 91.653,47.123 91.744,47.032 91.744,46.85 91.653,46.759 91.002,46.759 90.911,46.668 90.911,46.486 91.002,46.395 91.653,46.395 91.744,46.304 91.744,46.122 91.653,46.031 91.002,46.031 90.911,45.94 90.911,45.758 91.002,45.667 91.653,45.667 91.744,45.576 91.744,45.394 91.653,45.303 91.002,45.303 90.911,45.212 90.911,45.03 91.002,44.939 91.653,44.939 91.744,44.848 91.744,44.666 91.653,44.575 91.002,44.575 90.911,44.484 90.911,44.302 91.002,44.211 91.653,44.211 91.744,44.12 91.744,43.938 91.653,43.847 91.002,43.847 90.911,43.756 90.911,43.574 91.002,43.483 91.653,43.483 91.744,43.392 91.744,43.21 91.653,43.119 91.002,43.119 90.911,43.028 90.911,42.846 91.002,42.755 91.653,42.755 91.744,42.664 91.744,42.482 91.653,42.391 91.002,42.391 90.911,42.3 90.911,42.118 91.002,42.027 91.653,42.027 91.744,41.936 91.744,41.754 91.653,41.663 91.002,41.663 90.911,41.572 90.911,41.39 91.002,41.299 91.653,41.299 91.744,41.208 91.744,41.026 91.653,40.935 91.002,40.935 90.911,40.844 90.911,40.662 91.002,40.571 91.434,40.571 91.525,40.48 91.525,40.425 91.525,40.15 95.825,35.85 95.825,30.56 v1(91.58,26.315)
NetR180_2: R180.2 U40.16 | length 35.2
  Top Layer w0.11: U40.16@113.85,25.75 114.375,25.75 114.94,26.315 v1(116.58,26.315)
  Bottom Layer w0.11: R180.2@102.5,42.147 114.778,42.147 120.675,36.25 120.675,31.95 118.913,30.188 118.913,28.648 v1(116.58,26.315)
NetR181_1: R181.1 U36.F15 | length 1.8
  Top Layer w0.12: U36.F15@44.225,26.125 R181.1@46.025,26.125
NetR182_2: R182.2 U38.36 | length 2.5
  Top Layer w0.11: R182.2@56.525,25.575 57.2,25.575 57.425,25.35 U38.36@58.95,25.35
NetR183_2: R183.2 U39.36 | length 2.5
  Top Layer w0.11: R183.2@81.525,25.575 82.2,25.575 82.425,25.35 U39.36@83.95,25.35
NetR184_2: R184.2 U40.36 | length 2.5
  Top Layer w0.11: R184.2@106.525,25.575 107.2,25.575 107.425,25.35 U40.36@108.95,25.35
NetR185_2: R185.2 U38.15 | length 40.2
  Top Layer w0.11: U38.15@63.85,25.35 64.5,25.35 64.64,25.49 v1(66.58,25.49)
  Bottom Layer w0.11: v1(66.58,25.49) 67.45,26.36 67.45,28.05 70.825,31.425 70.825,39.85 R185.2@85.913,54.938
NetR186_2: R186.2 U39.15 | length 48.3
  Top Layer w0.11: U39.15@88.85,25.35 89.5,25.35 89.64,25.49 v1(91.58,25.49)
  Bottom Layer w0.11: v1(91.58,25.49) 96.325,30.235 96.325,35.95 92.6,39.675 92.6,40 92.6,40.055 92.509,40.146 92.161,40.146 92.07,40.237 92.07,40.419 92.161,40.51 92.641,40.51 92.732,40.601 92.732,40.783 92.641,40.874 92.161,40.874 92.07,40.965 92.07,41.147 92.161,41.238 92.641,41.238 92.732,41.329 92.732,41.511 92.641,41.602 92.161,41.602 92.07,41.693 92.07,41.875 92.161,41.966 92.641,41.966 92.732,42.057 92.732,42.239 92.641,42.33 92.161,42.33 92.07,42.421 92.07,42.603 92.161,42.694 92.641,42.694 92.732,42.785 92.732,42.967 92.641,43.058 92.161,43.058 92.07,43.149 92.07,43.331 92.161,43.422 92.641,43.422 92.732,43.513 92.732,43.695 92.641,43.786 92.161,43.786 92.07,43.877 92.07,44.059 92.161,44.15 92.641,44.15 92.732,44.241 92.732,44.423 92.641,44.514 92.161,44.514 92.07,44.605 92.07,44.787 92.161,44.878 92.641,44.878 92.732,44.969 92.732,45.151 92.641,45.242 92.161,45.242 92.07,45.333 92.07,45.515 92.161,45.606 92.641,45.606 92.732,45.697 92.732,45.879 92.641,45.97 92.161,45.97 92.07,46.061 92.07,46.243 92.161,46.334 92.641,46.334 92.732,46.425 92.732,46.607 92.641,46.698 92.161,46.698 92.07,46.789 92.07,46.971 92.161,47.062 92.509,47.062 92.6,47.153 92.6,47.275 92.6,47.4 89.375,50.625 89.375,52 R186.2@91.738,54.363
NetR187_2: R187.2 U40.15 | length 38.2
  Top Layer w0.11: U40.15@113.85,25.35 114.5,25.35 114.64,25.49 v1(116.58,25.49)
  Bottom Layer w0.11: R187.2@100.95,42.625 114.906,42.625 ; 114.904,42.55 121.075,36.379 121.075,31.675 119.6,30.2 119.6,28.51 v1(116.58,25.49)
NetR188_2: R188.2 R196.2 U38.37 | length 3.5
  Top Layer w0.11: R196.2@56.525,23.65 R188.2@56.525,24.575 57.05,24.575 57.455,24.98 58.95,24.98 U38.37@58.95,24.95
NetR189_2: R189.2 R197.2 U39.37 | length 3.5
  Top Layer w0.11: R197.2@81.525,23.65 R189.2@81.525,24.575 82.05,24.575 82.455,24.98 83.95,24.98 U39.37@83.95,24.95
NetR190_2: R190.2 R198.2 U40.37 | length 3.5
  Top Layer w0.11: R198.2@106.525,23.65 R190.2@106.525,24.575 107.05,24.575 107.455,24.98 108.95,24.98 U40.37@108.95,24.95
NetR194_1: R194.1 U36.J15 | length 1.8
  Top Layer w0.12: U36.J15@44.225,24.175 R194.1@46.025,24.175
NetR199_1: R199.1 U38.39 | length 1.4
  Top Layer w0.15: R199.1@57.775,23.6 57.87,23.6 58.42,24.15 U38.39@58.95,24.15
NetR200_1: R200.1 U39.39 | length 1.4
  Top Layer w0.15: R200.1@82.775,23.6 82.87,23.6 83.42,24.15 U39.39@83.95,24.15
NetR201_1: R201.1 U40.39 | length 1.4
  Top Layer w0.15: R201.1@107.775,23.6 107.87,23.6 108.42,24.15 U40.39@108.95,24.15
NetR211_2: R211.2 U36.R13 | length 1.7
  Top Layer w0.2: R211.2@42.925,18.555 U36.R13@42.925,20.275
NetR212_1: R212.1 U36.P3 | length 7.3
  Top Layer w0.12: R212.1@31,18.425 31,19.325 31.25,19.575 35.56,19.575 36.125,20.14 36.125,20.625 U36.P3@36.425,20.925
NetR223_1: R223.1 R326.2 R327.2 U50.20 | length 3.8
  Top Layer w0.2: U50.20@163.575,12.05 164.175,12.05 164.575,12.45 R223.1@164.575,13.225 ; R223.1@164.595,13.325 164.597,13.328 R326.2@164.597,14.327 ; R326.2@164.6,14.4 164.613,14.412 164.613,15.212 R327.2@164.65,15.25
NetR231_1: R231.1 R232.2 U50.11 | length 2.3
  Top Layer w0.3: R232.2@160.65,6.845 R231.1@160.65,8 U50.11@160.65,9.125
NetR240_1: R240.1 R241.1 R242.1 U52.7 | length 3.2
  Top Layer w0.2: R240.1@27.72,5 R241.1@28.795,5 R242.1@29.87,5 30.02,5.15 U52.7@30.825,5.15
NetR243_2: R243.2 R244.2 U53.1 | length 3.1
  Top Layer w0.3: U53.1@55.263,63.038 55.287,63.063 R243.2@56.988,63.063 56.988,61.712 R244.2@57,61.7
NetR250_1: R250.1 U27.E8 | length 2.6
  Top Layer w0.09: v2@90.8,78 U27.E8@91.2,77.6
  Bottom Layer w0.2: R250.1@89.875,79.4 89.875,78.575 90.05,78.4 90.4,78.4 v2(90.8,78)
NetR251_1: R251.1 U27.E6 | length 2.1
  Top Layer w0.1: v2(89.2,78) U27.E6@89.6,77.6
  Bottom Layer w0.2: R251.1@88.825,79.4 88.868,79.358 88.868,79.033 89.2,78.7 v2(89.2,78)
NetR262_2: R262.2 U27.K16 | length 1.4
  Top Layer w0.11: U27.K16@97.6,73.6 97.657,73.6 v2@97.966,73.291
  Bottom Layer w0.11: R262.2@97.924,74.149 97.978,74.096 v2(97.975,73.3)
NetR274_1: R274.1 U27.V16 | length 1.2
  Top Layer w0.1: U27.V16@97.6,67.2 v2(98,66.8)
  Bottom Layer w0.2: R274.1@97.35,66.825 97.375,66.8 v2(98,66.8)
NetR285_2: R285.2 U27.Y20 | length 1.1
  Top Layer w0.09: U27.Y20@100.8,65.6 v2@101.138,65.262
  Bottom Layer w0.09: R285.2@101.15,64.75 R285.2@101.2,64.7
  Bottom Layer w0.3: R285.2@101.15,64.75 v2(101.15,65.275)
NetR287_1: R287.1 U27.V17 | length 5.6
  Top Layer w0.1: U27.V17@98.4,67.2 v2(98.8,66.8)
  Bottom Layer w0.1: R287.1@98.05,62.075 98.05,62.731 98.465,63.146 98.465,66.465 v2(98.8,66.8)
NetTP9_1: TP9.1 U24.H5 | length 7.4
  Top Layer w0.09: 110.525,87 110.525,88.468 110.775,88.718 U24.H5@110.775,89.35
  Top Layer w0.11: 110.525,87 110.775,86.75 112.106,86.75 112.43,86.426 TP9.1@112.43,83.629
NetTP10_1: TP10.1 U27.L20 | length 11.7
  Top Layer w0.1: v2(100.5,72.4) 100.5,72.45 100.8,72.75 U27.L20@100.8,72.8 ; v2(103.75,81.4) TP10.1@104.575,81.4
  Signal Layer 2 w0.1: v2(100.5,72.4) 100.5,73 101.05,73.55 101.05,78.7 v2(103.75,81.4)
NetTP12_1: TP12.1 U27.U4 | length 16.5
  Top Layer w0.1: TP12.1@72,68.975 v1(74.15,68.975) ; v2@87.6,68.4 U27.U4@88,68
  Signal Layer 2 w0.1: v1(74.15,68.975) 87,68.975 v2(87.675,68.3)
NetTP26_1: TP26.1 U36.B2 | length 6.4
  Top Layer w0.12: v1(34.825,32.55) 34.825,30.725 35.475,30.075 35.475,29.025 U36.B2@35.775,28.725
  Bottom Layer w0.12: TP26.1@33.25,34.125 v1(34.825,32.55)
NetTP27_1: TP27.1 U36.B3 | length 6
  Top Layer w0.12: v1(36.2,33.325) 36.2,32.875 36.35,32.725 36.35,30.386 36.125,30.161 36.125,29.025 U36.B3@36.425,28.725
  Bottom Layer w0.12: v1(36.2,33.325) TP27.1@37,34.125
NetTP28_1: TP28.1 U36.B1 | length 7
  Top Layer w0.12: v1(32.6,32.9) 33.625,31.875 33.625,30.225 U36.B1@35.125,28.725
  Bottom Layer w0.12: TP28.1@31.375,34.125 v1(32.6,32.9)
NetTP29_1: TP29.1 U36.A2 | length 5
  Top Layer w0.12: U36.A2@35.775,29.375 35.775,31.7 v1(35.775,32.55)
  Bottom Layer w0.12: TP29.1@35.125,34.125 35.125,33.2 v1(35.775,32.55)
NetTP31_1: TP31.1 U40.35 | length 8.5
  Top Layer w0.11: TP31.1@102.2,29.925 104.525,27.6 106.025,27.6 106.925,26.7 107.875,25.75 U40.35@108.95,25.75
NetTP32_1: TP32.1 U34.12 | length 2.4
  Top Layer w0.2: U34.12@130.75,30.5 131.6,30.5 132.025,30.075 132.311,30.075 TP32.1@132.811,29.575
NetTP38_1: TP38.1 U50.4 | length 1.7
  Top Layer w0.3: U50.4@161.15,12.975 TP38.1@161.15,14.704
NJTRST: TP13.1 U27.AA2 | length 4
  Top Layer w0.1: TP13.1@83.838,62.335 84.635,63.132 84.635,63.791 85.244,64.4 86,64.4 U27.AA2@86.4,64.8
NRST: B1.1 B1.2 C336.2 CN22.10 R7.1 R21.1 R38.1 R212.2 U10.1 U27.U3 | length 289.9
  Top Layer w0.09: 85.884,67.915 85.894,67.905 87.105,67.905 U27.U3@87.2,68
  Top Layer w0.1: B1.1@19.023,120.45 B1.2@11.073,120.45 U10.1@11.073,118.875 R7.1@12.123,118.875 12.173,118.825 v1(22.55,118.825) ; v1(28.1,93.6) 53.475,93.6 55,92.075 55,90.927 57.477,90.927 60.15,93.6 v1(67.1,93.6) ; v1(64.5,66.35) 64.95,66.8 68.825,66.8 69.275,66.35 69.275,64.375 69.625,64.025 71.625,64.025 71.85,63.8 71.85,63.275 72.1,63.025 74.65,63.025 75,63.375 78.765,63.375 81.44,66.05 82.468,66.05 84.332,67.915 85.884,67.915
  Top Layer w0.15: v1(31,16.88) R212.2@31,17.525
  Top Layer w0.2: R21.1@100.5,110.15 v1(101.175,110.15)
  Top Layer w0.4: CN22.10@69.535,43.585 71.545,43.585 v1(71.55,43.58)
  Signal Layer 2 w0.1: v1(31,16.88) 31,18.475 33.525,21 33.525,23.26 34.15,23.885 34.15,33.017 35.978,34.845 40.387,34.845 41.067,35.525 44.7,35.525 45.5,34.725 48.95,34.725 52.136,34.725 58.461,41.05 61.125,41.05 v1(61.55,41.475) 61.975,41.05 69.02,41.05 v1(71.55,43.58) ; v1(67.05,106.225) 68,107.175 96,107.175 97.575,105.6 98.825,105.6 101.175,107.95 v1(101.175,110.15)
  Bottom Layer w0.1: v1(22.55,118.825) 22.55,105.925 28.1,100.375 v1(28.1,93.6) ; v1(61.55,41.475) 62.142,41.475 64.075,43.408 64.075,65.925 v1(64.5,66.35) 65.3,66.35 66.675,67.725 66.675,83 69.1,85.425 69.1,91.6 v1(67.1,93.6) 67.1,106.175 v1(67.05,106.225)
NRSTC1MS: D5.2 R22.1 R27.1 R59.1 R272.1 U27.T3 | length 135
  Top Layer w0.1: v2(86.131,68.44) 86.45,68.44 86.49,68.48 86.88,68.48 U27.T3@87.2,68.8 ; v1(97.768,106.15) 97.768,107.384 98.109,107.725 R27.1@98.709,107.725 R22.1@98.709,108.7
  Top Layer w0.15: R59.1@39.225,67.8 39.25,67.775 v1(39.25,65.75)
  Signal Layer 2 w0.1: v1(39.25,65.75) 39.275,65.725 56.233,65.725 56.608,66.1 63.225,66.1 64.05,66.925 64.875,66.925 65.7,66.1 72.582,66.1 72.755,66.273 74.15,66.273 75.402,67.525 83.075,67.525 83.99,68.44 v2(86.131,68.44) ; v1(82.75,109.125) 86.75,109.125 88.5,107.375 96.543,107.375 v1(97.768,106.15)
  Bottom Layer w0.1: v1(82.75,109.125) 81.245,107.62 81.245,69.692 82.237,68.7 R272.1@84.1,68.7 85.87,68.7 v2(86.131,68.44) ; v1(97.768,106.15) 104.175,99.743 D5.2@104.175,90.77
OSC32_IN: C86.1 U27.R1 X1.2 | length 12.2
  Top Layer w0.09: C86.1@77.85,65.9 77.85,66.725 78,66.875 79.835,66.875 80,67.04 80,68.544 80.444,68.988 82.817,68.988 83.735,69.905 85.295,69.905 U27.R1@85.6,69.6
  Top Layer w0.1: X1.2@76.525,65.9 C86.1@77.85,65.9
OSC32_OUT: R64.1 U27.R2 | length 8.7
  Top Layer w0.09: R64.1@79.6,67.45 79.6,68.413 80.365,69.178 81.172,69.178 ; 81.172,69.175 82.75,69.175 83.66,70.085 85.532,70.085 86.017,69.6 U27.R2@86.4,69.6
PA0_WKUP: U26.32 U27.Y2 | length 60.1
  Top Layer w0.09: v2(86.15,65.175) 86.376,65.401 86.376,65.576 U27.Y2@86.4,65.6
  Top Layer w0.15: v3(49,83.227) 49,82.48 49.1,82.38 U26.32@49.1,81.797
  Signal Layer 2 w0.1: v1(49.375,64.125) 49.875,64.625 55.981,64.625 56.856,65.5 69.775,65.5 70.9,64.375 78.6,64.375 79.4,65.175 v2(86.15,65.175)
  Bottom Layer w0.1: v3(49,83.227) 49,81.8 49.675,81.125 49.675,72.75 48.825,71.9 48.825,64.675 v1(49.375,64.125)
PCIE.CLKIN_N: R83.1 R88.2 R288.2 U27.AA18 | length 20.8
  Top Layer w0.09: U27.AA18@99.2,64.8 99.166,64.834 98.961,64.834 98.875,64.749 98.875,63.825 99.3,63.4 99.3,61.425 99.525,61.2 99.525,57.395 104.445,52.475 104.901,52.475 105.225,52.151 105.225,51.903 105.475,51.653 v1(105.475,51.648) 105.225,51.398 105.225,51.213 105.32,51.118 105.415,51.118 105.625,50.908 R83.1@105.625,50.813 ; R88.2@105.625,49.84 105.415,50.05 105.281,50.05 105.225,50.106 105.225,50.252 105.225,50.365 105.32,50.46 105.415,50.46 R83.1@105.625,50.67
  Bottom Layer w0.09: v1(105.475,51.648) 105.475,51.653 105.225,51.903 105.225,52.912 105.278,52.965 105.415,52.965 R288.2@105.625,53.175
PCIE.CLKIN_P: R82.1 R87.2 R328.2 U27.Y18 | length 21.5
  Top Layer w0.09: U27.Y18@99.2,65.6 99.192,65.592 99.192,65.381 99.035,65.224 98.997,65.224 98.625,64.852 98.625,63.721 99.05,63.296 99.05,61.321 99.275,61.096 99.275,57.291 104.342,52.225 104.797,52.225 104.975,52.047 104.975,51.903 104.725,51.653 v1(104.725,51.648) 104.975,51.398 104.975,51.213 104.88,51.118 104.785,51.118 104.575,50.908 R82.1@104.575,50.813 ; R87.2@104.575,49.84 104.785,50.05 104.919,50.05 104.975,50.106 104.975,50.365 104.88,50.46 104.785,50.46 R82.1@104.575,50.67
  Bottom Layer w0.09: R328.2@104.575,53.175 104.785,52.965 104.922,52.965 104.975,52.912 104.975,51.903 104.725,51.653 v1(104.725,51.648)
PCIE.CLKOUT_N: CN13.11 R78.2 R84.2 R89.2 R288.1 | length 56.2
  Top Layer w0.09: v1@106.425,56.335 v1@106.425,56.345 ; R78.2@106.575,57.175 106.365,56.965 106.231,56.965 106.175,56.909 106.175,56.615 106.425,56.365 v1(106.425,56.35) v1@106.425,56.345 ; R89.2@108.225,49.84 108.435,50.05 108.569,50.05 108.625,50.106 108.625,50.252 108.625,50.365 108.53,50.46 108.435,50.46 108.225,50.67 R84.2@108.225,50.765 108.225,50.86 108.435,51.07 108.53,51.07 108.625,51.165 108.625,51.35 v1(108.375,51.6) ; CN13.11@139,52.7 137.955,52.7 137.68,52.425 136.55,52.425 136.1,51.975 136.1,49.5 134.9,48.3 133.025,48.3 125.645,55.68 106.27,55.68 106.175,55.775 106.175,56.095 v1@106.425,56.345
  Bottom Layer w0.09: R288.1@105.625,54.075 105.415,54.285 105.278,54.285 105.225,54.338 105.225,54.972 105.453,55.2 105.8,55.2 106.175,55.575 106.175,56.095 106.425,56.345 v1(106.425,56.35) 106.425,56.355 106.175,56.605 106.175,57.259 106.466,57.55 108.121,57.55 108.625,57.046 108.625,51.855 108.375,51.605 v1(108.375,51.6)
PCIE.CLKOUT_P: CN13.13 R77.2 R85.2 R90.2 R328.1 | length 57.4
  Top Layer w0.09: R77.2@105.525,57.175 105.735,56.965 105.87,56.965 105.925,56.909 105.925,56.615 105.675,56.365 v1(105.675,56.35) 105.675,56.345 105.925,56.095 105.925,55.7 106.175,55.45 125.55,55.45 132.95,48.05 135.004,48.05 136.35,49.396 136.35,51.871 136.654,52.175 137.523,52.175 137.68,52.175 137.955,51.9 CN13.13@139,51.9 ; v1(109.125,51.6) 108.875,51.35 108.875,51.165 108.97,51.07 109.065,51.07 109.275,50.86 R85.2@109.275,50.765 109.275,50.67 109.065,50.46 108.97,50.46 108.875,50.365 108.875,50.106 108.931,50.05 109.065,50.05 R90.2@109.275,49.84
  Bottom Layer w0.09: R328.1@104.575,54.075 104.785,54.285 104.922,54.285 104.975,54.338 104.975,55.076 105.349,55.45 105.696,55.45 105.925,55.679 105.925,56.095 105.675,56.345 v1(105.675,56.35) 105.675,56.355 105.925,56.605 105.925,57.363 106.362,57.8 108.225,57.8 108.875,57.15 108.875,51.855 109.125,51.605 v1(109.125,51.6)
PCIE.CLKREQN: CN13.7 Q4.1 R91.1 U27.U15 | length 73.2
  Top Layer w0.1: U27.U15@96.8,68 96.8,68.054 97.08,68.334 v2(97.08,68.4) ; R91.1@100.6,48.375 v1(100.6,47.605) 101.45,46.755 101.45,45.95 102.11,45.29 Q4.1@103.325,45.29 ; v1(131.8,56.6) 134.1,54.3 CN13.7@139,54.3
  Bottom Layer w0.1: 96.055,66.185 96.055,67.391 96.105,67.441 96.105,68.626 96.31,68.831 96.649,68.831 v2(97.08,68.4) ; 96.066,66.185 96.425,65.826 96.425,53.629 97.1,52.954 97.1,51.105 v1(100.6,47.605) 101.28,46.925 122.125,46.925 v1(131.8,56.6)
PCIE.NWAKE: CN13.1 U27.AA15 | length 65.9
  Top Layer w0.09: 96.515,60.625 96.515,64.317 96.8,64.602 U27.AA15@96.8,64.8
  Top Layer w0.1: v1(96.475,47.425) 95.675,48.225 95.675,59.8 96.5,60.625 ; v1(132.85,56.6) 133.85,57.6 136.725,57.6 137.625,56.7 CN13.1@139,56.7
  Bottom Layer w0.1: v1(96.475,47.425) 100.1,47.425 100.8,46.725 122.526,46.725 132.401,56.6 v1(132.85,56.6)
PCIE.RSTN: CN13.22 R96.1 U27.M2 | length 112.6
  Top Layer w0.09: 81.172,72.285 85.732,72.285 86.017,72 U27.M2@86.4,72
  Top Layer w0.1: v1(72.954,73.358) 74.027,72.285 81.172,72.285
  Top Layer w0.2: v1(145.656,45.1) CN13.22@147.243,45.1
  Signal Layer 2 w0.1: v1(75.35,56) 84.34,56 84.975,55.365 87.893,55.365 88.472,54.787 94.702,54.787 97.756,51.733 97.756,49.244 100.275,46.725 140.608,46.725 142.233,45.1 v1(145.656,45.1)
  Bottom Layer w0.1: v1(72.954,73.358) 73.275,73.037 R96.1@73.275,72.125 73.275,71.4 72.075,70.2 72.075,56.925 73,56 v1(75.35,56)
PCIE.RX1_N: CN13.23 U27.AB20 | length 49.4
  Top Layer w0.09: U27.AB20@100.76,64.04 100.709,63.989 100.588,63.989 100.535,63.937 100.535,63.79 100.775,63.55 100.775,62.875 101.4,62.25 101.469,62.181 102.03,61.62 102.03,58.673 102.03,58.22 105.825,54.425 125.054,54.425 127.112,52.367 135.054,44.425 137.68,44.425 137.955,44.7 CN13.23@139,44.7
PCIE.RX1_P: CN13.25 U27.AA20 | length 50.6
  Top Layer w0.09: U27.AA20@100.76,64.76 100.76,64.581 100.285,64.106 100.285,63.687 100.525,63.446 100.525,62.771 101.78,61.516 101.78,58.569 101.78,58.116 105.721,54.175 124.95,54.175 126.85,52.275 134.95,44.175 137.68,44.175 137.955,43.9 CN13.25@139,43.9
